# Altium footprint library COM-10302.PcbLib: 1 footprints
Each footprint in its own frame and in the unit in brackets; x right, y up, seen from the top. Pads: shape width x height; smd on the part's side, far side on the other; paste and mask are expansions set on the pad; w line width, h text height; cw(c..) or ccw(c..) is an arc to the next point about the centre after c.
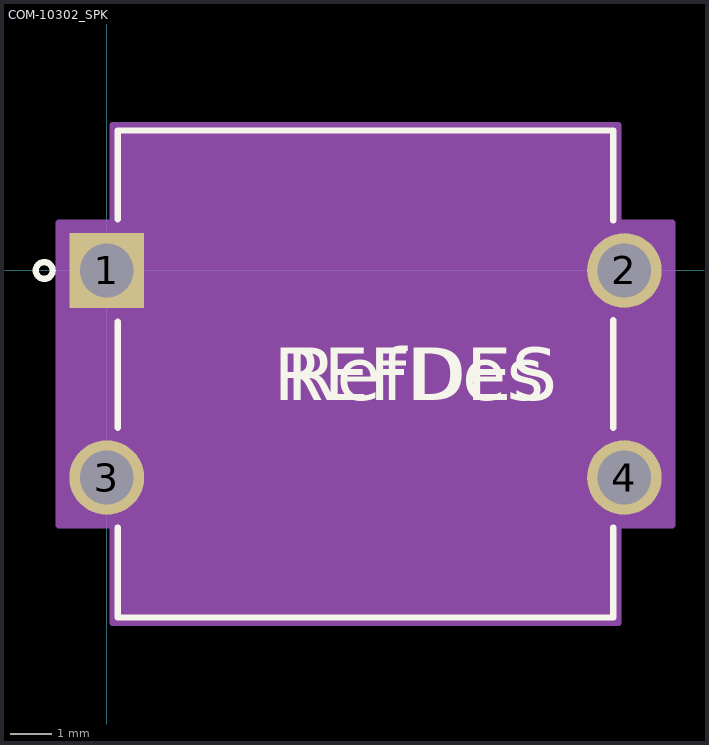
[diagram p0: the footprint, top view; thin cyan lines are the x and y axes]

## COM-10302_SPK [mil]
pads (4):
  rect 71x71 / inner round 60 / far side rect 71x71 hole 51 paste-35.5 mask+0: 1(0,0)
  round 71 / inner round 60 / far side round 71 hole 51 paste-35.5 mask+0: 2(492.13,0) 3(0,-196.85) 4(492.13,-196.85)
Top Overlay:
  circle w6: c-59.44,0 r8
  lines w6: 10.56,-244.29 10.56,-329.93 481.56,-329.93 481.56,-244.29 ; 10.56,-149.41 10.56,-48.6 ; 10.56,48.6 10.56,133.07 481.56,133.07 481.56,47.44 ; 481.56,-149.41 481.56,-47.44
  text "RefDes" at 171.06,-123.43 h50
  text "REFDES" at 158.56,-123.43 h50
Mechanical 13:
  circle w6: c15.56,100 r8
  circle w0: c246.06,-98.43 r75
  lines w1: -25.5,-222.35 -25.5,-171.35 15.56,-171.35 15.56,-222.35 -25.5,-222.35 ; -25.5,-25.5 -25.5,25.5 15.56,25.5 15.56,-25.5 -25.5,-25.5 ; 15.56,-324.93 476.56,-324.93 476.56,128.07 15.56,128.07 15.56,-324.93 ; 476.56,-222.35 476.56,-171.35 517.63,-171.35 517.63,-222.35 476.56,-222.35 ; 476.56,-25.5 476.56,25.5 517.63,25.5 517.63,-25.5 476.56,-25.5
  text "RefDes2" at 158.56,-123.43 h50
Mechanical 15:
  region: 5.56,-242.35 -45.5,-242.35 -45.5,45.5 5.56,45.5 5.56,138.07 486.56,138.07 486.56,45.5 537.63,45.5 537.63,-242.35 486.56,-242.35 486.56,-334.93 5.56,-334.93
  lines w6: -45.5,-242.35 -45.5,45.5 5.56,45.5 5.56,138.07 486.56,138.07 486.56,45.5 537.63,45.5 537.63,-242.35 486.56,-242.35 486.56,-334.93 5.56,-334.93 5.56,-242.35 -45.5,-242.35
